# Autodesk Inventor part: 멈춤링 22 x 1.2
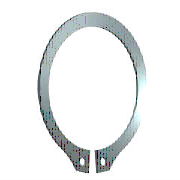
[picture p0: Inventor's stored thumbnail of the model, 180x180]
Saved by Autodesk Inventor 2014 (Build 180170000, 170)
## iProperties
IsCustomPart: 0
Company: 한국ATC센터
Created: 2009-02
Part Number: 멈춤링 22 x 1.2
Material: Steel, Mild
Description: 리테이닝 링(C형)
Document SubType Name: Modeling
Standard: KS B 1336
Designer: KYOUNG IL JANG
Standards Organization: KS
Language: ko-KR
Size Designation: 22 x 1.2
Categories: <MemberInstance><Categories><Category DisplayName="샤프트 부품" InternalName="7f7aeb1f-a693-4053-b835-cee3144e0d98" Mnemonic="SHFT"><Category DisplayName="써클립" Inter
Density: 7.86 g/cm^3
Mass: 1.8286 g
Surface Area: 5.91219 cm^2
Volume: 0.232646 cm^3
Appearance: Metal-Steel
Author: KYOUNG IL JANG
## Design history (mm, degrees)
sketch "스케치1"
  geometry: L1 (-6, 0)-(6, 0) reference; L2 (0, 20.189)-(0, -80.536) reference; L3 (-48.09, 0)-(48.09, 0) reference; L4 (-0.5, -21.488)-(-0.5, -25.588); L5 (-0.5, -6.54)-(-0.5, -13.29); L6 (-2.795, 2.7)-(3.672, 2.7); L7 (0.5, -6.54)-(0.5, -13.29); L8 (0.5, -21.488)-(0.5, -25.588); C1 r 1 at (-2, -23.437); C2 r 1 at (2, -23.437); A1 r 10.5 centre (0, -11) between (0.5, -21.488) and (-0.5, -21.488); A2 r 13.025 centre (0, -10.325) between (5.149, -22.289) and (-5.149, -22.289); A3 r 14.597 centre (0, -11) between (-2.318, -25.411) and (-0.5, -25.588); A4 r 2 centre (-2, -23.437) between (-3.97, -23.781) and (-2.318, -25.411); A5 r 2 centre (-5.94, -24.126) between (-3.97, -23.781) and (-5.149, -22.289); A6 r 2 centre (5.94, -24.126) between (5.149, -22.289) and (3.97, -23.781); A7 r 2 centre (2, -23.437) between (2.318, -25.411) and (3.97, -23.781); A8 r 14.597 centre (0, -11) between (0.5, -25.588) and (2.318, -25.411)
  constraints: 16 point on circle, 12 end point, 10 centre point, 9 symmetric about line, 5 point on line, 4 tangent, 3 coincident, 2 horizontal, 1 perpendicular, 1 vertical, 5 other
  dimensions: "d0" = 21 diameter of A1 (= ND); "d1" = 4.1 distance of L4.end L4.start (= SRB2); "d6" = 0.5 distance between parallel lines of L2 L5 (= 0.25 x SD5); "d7" = 2.7 distance between parallel lines of L6 L3 (= SRB1); "d8" = 0.675 distance of A1.centre A2.centre (= 0.25 x SRB1); "d9" = 2 radius of A4 (= SD5); "d10" = 2 radius of A5 (= SD5); "d11" = 1.5 distance from line of L4 A4.centre (= 0.75 x SD5); "d12" = 2 diameter of C1 (= SD5); "d13" = 2 diameter of C2 (= SD5); "d14" = 11 distance from line of A1.centre L1 (= 0.5 x WD)
extrude "본체" new body sketch "스케치1" distance "d2" = 1.2 (= SD); taper "d3" = 0 deg
workaxis "Work Axis1"
workplane "Work Plane1"
body "Solid1"
other parameters: "WD" = 22 (= WDMIN) [user parameter; used in 1 equation term], "SD" = 1.2 [user parameter; used in 1 equation term], "SRB1" = 2.7 [user parameter; used in 2 equation terms], "ND" = 21 [user parameter; used in 1 equation term], "SRB2" = 4.1 [user parameter; used in 1 equation term], "SD5" = 2 [user parameter; used in 6 equation terms], "d15" = 0, "d16" = 0, "d17" = 0, "d41" = 0, "d42" = 0, "WDMIN" = 22 [user parameter; used in 1 equation term], "SD3" = 20.5 [user parameter], "WDMAX" = 24 [user parameter]
